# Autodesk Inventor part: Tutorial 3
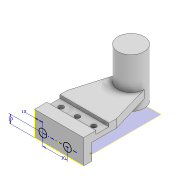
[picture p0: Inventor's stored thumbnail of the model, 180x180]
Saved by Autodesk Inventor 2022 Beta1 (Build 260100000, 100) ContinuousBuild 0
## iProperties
Created: 2021-03
Part Number: Tutorial 3
Material: Generic
Document SubType Name: Modeling
Designer: ASUS Laptop
Density: 1 g/cm^3
Appearance: Default
Author: ASUS Laptop
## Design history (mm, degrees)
sketch "Sketch1"
  geometry: L1 (0, 0)-(30, 0); L2 (30, 0)-(30, -15); L3 (30, -15)-(26, -15); L4 (26, -15)-(26, -31); L5 (26, -31)-(30, -31); L6 (30, -31)-(30, -40); L7 (20, -40)-(20, -10); L8 (20, -10)-(0, -10); L9 (0, -10)-(0, 0); L10 (20, -40)-(30, -40)
  constraints: 20 end point, 8 perpendicular, 1 horizontal, 1 parallel, 1 point on line
  dimensions: "d0" = 16 distance of L3.end L4.end; "d1" = 15 distance of L1.end L2.end; "d2" = 40 distance between parallel lines of L1 L10; "d3" = 30 distance between parallel lines of L9 L2; "d4" = 4 distance between parallel lines of L4 L2; "d5" = 10 distance between parallel lines of L8 L1
extrude "Extrusion1" new body sketch "Sketch1" stored distance "d6" = 60; taper "d7" = 0 deg
sketch "Sketch4"
  geometry: L1 (0, 9)-(60, 9) reference; L2 (0, 9)-(14, 57); L3 (14, 57)-(46, 57); L4 (46, 57)-(60, 9); L5 (60, 9)-(0, 9); L6 (30, -31)-(30, 84.04)
  constraints: 10 end point, 1 collinear, 1 parallel, 1 vertical, 1 other
  dimensions: "d8" = 32 distance of L2.end L3.end; "d9" = 48 distance between parallel lines of L3 L1
extrude "Extrusion2" join sketch "Sketch4" distance "d10" = 10; taper "d11" = 0 deg
workplane "Work Plane1"
sketch "Sketch5"
  geometry: L1 (14, -78)-(46, -78) reference; L2 (0, 0)-(0, 10) reference; C1 r 16 at (30, -78); 1 further point
  constraints: 1 centre point, 1 midpoint
  dimensions: "d13" = 32 diameter of C1; "d14" = 30 distance from line of L2 C1.centre
extrude "Extrusion3" join sketch "Sketch5" distance "d15" = 60; taper "d16" = 0 deg
sketch "Sketch6"
  geometry: L1 (-6.213, 7.5)-(70.808, 7.5); L2 (0, -15)-(60, -15) reference; L3 (0, 0)-(0, 16) reference; C1 r 3 at (10, 7.5); C2 r 3 at (30, 7.5); C3 r 3 at (50, 7.5); 1 further point
  constraints: 3 centre point, 3 point on line, 2 end point, 2 equal radius, 1 horizontal
  dimensions: "d17" = 22.5 distance between parallel lines of L2 L1; "d18" = 10 distance from line of C1.centre L3; "d19" = 20 distance of C2.centre C1.centre; "d20" = 20 distance of C3.centre C2.centre; "d21" = 6 diameter of C1
extrude "Extrusion4" cut sketch "Sketch6" distance "d22" = 60; taper "d23" = 0 deg
sketch "Sketch7"
  geometry: 1 further point
sketch "Sketch8"
  geometry: L1 (10, 10)-(52.331, 10); L2 (0, 0)-(60, 0) reference; L3 (0, 0)-(0, 30) reference; C1 r 4.789 at (10, 10); C2 r 4.789 at (40, 10); 1 further point
  constraints: 2 centre point, 2 end point, 1 equal radius, 1 horizontal, 1 point on line
  dimensions: "d24" = 10 distance between parallel lines of L2 L1; "d25" = 10 distance from line of L3 L1.start; "d26" = 30 distance of C2.centre L1.start
body "Solid1"
